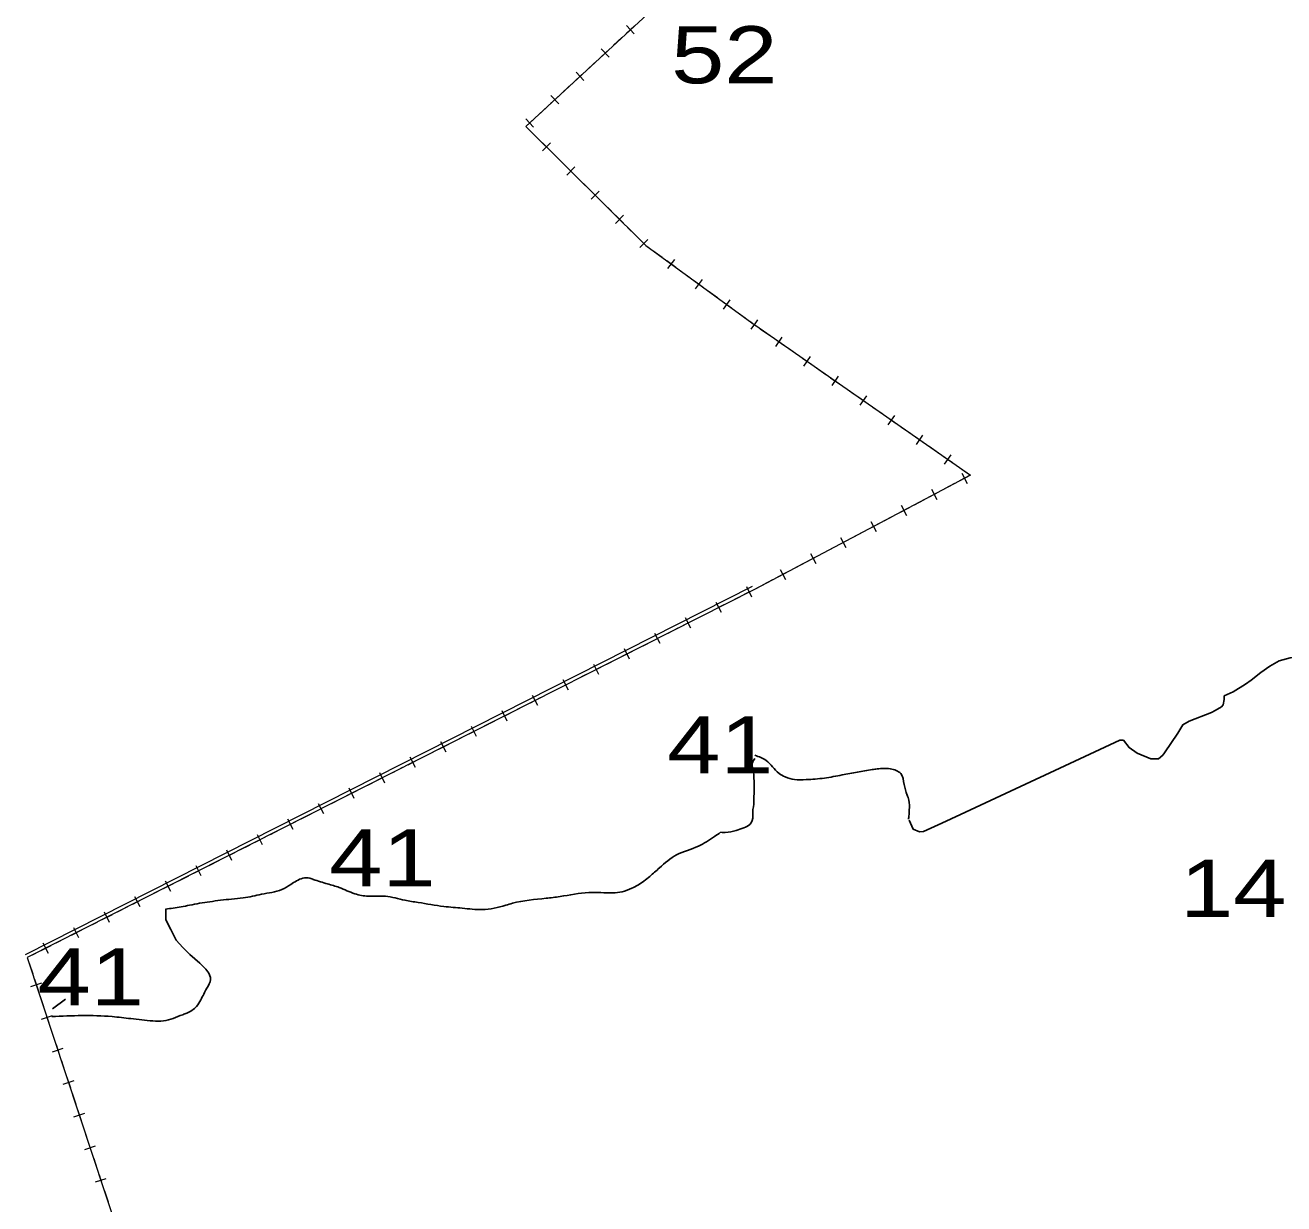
# Model space of a CAD drawing. Extents: x 476989 to 498418, y 4381813 to 4416555.
# Drawn here: x 483464 to 484565, y 4384627 to 4385658 of the extents above; entities that cross this region are included whole.
import ezdxf
from ezdxf.enums import TextEntityAlignment as Align

# ---------------------------------------------------------------- set-up
doc = ezdxf.new("R2010")
doc.units = 0
doc.header["$LTSCALE"] = 20
for name, color, linetype, lineweight in [('13', 7, 'Continuous', 13), ('34', 7, 'Continuous', 13), ('6', 7, 'Continuous', 25)]:
    doc.layers.add(name, color=color, linetype=linetype, lineweight=lineweight)

msp = doc.modelspace()

# ---------------------------------------------------------------- linework, layer by layer
at = {"layer": '34'}
for p, q in [((483986.15, 4385646.82), (483978.81, 4385640.03)), ((483997.17, 4385657), (483989.82, 4385650.21)), ((483990.1, 4385657.28), (483996.89, 4385649.94)), ((483975.14, 4385636.64), (483967.8, 4385629.85)), ((483968.07, 4385636.91), (483974.86, 4385629.57)), ((483964.13, 4385626.45), (483956.79, 4385619.66)), ((483953.11, 4385616.27), (483945.77, 4385609.48)), ((483946.05, 4385616.54), (483952.84, 4385609.2)), ((483942.1, 4385606.08), (483934.76, 4385599.29)), ((483931.09, 4385595.9), (483923.75, 4385589.11)), ((483924.02, 4385596.18), (483930.81, 4385588.83)), ((483920.08, 4385585.71), (483912.73, 4385578.93)), ((483902, 4385575.81), (483908.79, 4385568.47)), ((483905.82, 4385565.21), (483912.93, 4385558.18)), ((483916.48, 4385554.66), (483923.58, 4385547.62)), ((483916.51, 4385547.59), (483923.55, 4385554.69)), ((483927.14, 4385544.1), (483934.24, 4385537.06)), ((483937.79, 4385533.55), (483944.9, 4385526.51)), ((483937.83, 4385526.48), (483944.87, 4385533.58)), ((483948.45, 4385522.99), (483955.56, 4385515.95)), ((483959.11, 4385512.43), (483966.21, 4385505.4)), ((483959.14, 4385505.36), (483966.18, 4385512.47)), ((483969.77, 4385501.88), (483976.87, 4385494.84)), ((483980.42, 4385491.32), (483987.53, 4385484.29)), ((483980.46, 4385484.25), (483987.49, 4385491.36)), ((483991.08, 4385480.77), (483998.19, 4385473.73)), ((484001.77, 4385463.14), (484008.81, 4385470.25)), ((484013.14, 4385460.53), (484021.22, 4385454.63)), ((484025.26, 4385451.69), (484033.34, 4385445.8)), ((484026.35, 4385444.7), (484032.24, 4385452.78)), ((484037.38, 4385442.85), (484045.46, 4385436.96)), ((484049.5, 4385434.01), (484057.58, 4385428.12)), ((484050.59, 4385427.03), (484056.48, 4385435.11)), ((484061.62, 4385425.18), (484069.7, 4385419.28)), ((484073.74, 4385416.34), (484081.82, 4385410.45)), ((484074.83, 4385409.35), (484080.72, 4385417.43)), ((484085.86, 4385407.5), (484093.94, 4385401.61)), ((484097.98, 4385398.66), (484103, 4385395)), ((484099.07, 4385391.68), (484103.23, 4385397.38)), ((484103.23, 4385397.38), (484104.96, 4385399.76)), ((484107.1, 4385392.14), (484115.31, 4385386.42)), ((484119.41, 4385383.57), (484127.61, 4385377.85)), ((484120.65, 4385376.61), (484126.37, 4385384.81)), ((484131.72, 4385374.99), (484139.92, 4385369.27)), ((484144.02, 4385366.41), (484152.23, 4385360.7)), ((484145.27, 4385359.45), (484150.98, 4385367.66)), ((484156.33, 4385357.84), (484164.53, 4385352.12)), ((484169.88, 4385342.3), (484175.6, 4385350.51)), ((484168.64, 4385349.26), (484176.84, 4385343.55)), ((484180.94, 4385340.69), (484189.15, 4385334.97)), ((484193.25, 4385332.11), (484201.46, 4385326.4)), ((484194.49, 4385325.15), (484200.21, 4385333.36)), ((484205.56, 4385323.54), (484213.76, 4385317.82)), ((484217.86, 4385314.96), (484226.07, 4385309.24)), ((484219.11, 4385308), (484224.83, 4385316.21)), ((484230.17, 4385306.39), (484238.38, 4385300.67)), ((484242.48, 4385297.81), (484250.68, 4385292.09)), ((484243.72, 4385290.85), (484249.44, 4385299.05)), ((484254.79, 4385289.23), (484262.99, 4385283.52)), ((484267.09, 4385280.66), (484275.3, 4385274.94)), ((484268.34, 4385273.7), (484274.05, 4385281.9)), ((484279.4, 4385272.08), (484287.6, 4385266.37)), ((484290.24, 4385263.6), (484281.4, 4385258.92)), ((484283.48, 4385265.68), (484288.16, 4385256.84)), ((484256.96, 4385251.65), (484261.64, 4385242.81)), ((484276.98, 4385256.58), (484268.14, 4385251.91)), ((484250.46, 4385242.55), (484241.62, 4385237.88)), ((484263.72, 4385249.57), (484254.88, 4385244.89)), ((484223.95, 4385228.52), (484215.11, 4385223.85)), ((484237.21, 4385235.54), (484228.37, 4385230.86)), ((484230.45, 4385237.62), (484235.12, 4385228.78)), ((484210.69, 4385221.51), (484201.85, 4385216.83)), ((484203.93, 4385223.59), (484208.61, 4385214.75)), ((484184.17, 4385207.48), (484175.33, 4385202.8)), ((484177.41, 4385209.56), (484182.09, 4385200.72)), ((484197.43, 4385214.49), (484188.59, 4385209.82)), ((484150.9, 4385195.53), (484155.57, 4385186.69)), ((484170.91, 4385200.46), (484162.07, 4385195.79)), ((484144.4, 4385186.43), (484135.56, 4385181.75)), ((484157.65, 4385193.45), (484148.82, 4385188.77)), ((484131.14, 4385179.42), (484122.3, 4385174.74)), ((484124.38, 4385181.5), (484129.06, 4385172.66)), ((484100.12, 4385166.55), (483464.12, 4384844.55)), ((484100.12, 4385166.55), (483464.12, 4384844.55)), ((484102, 4385164), (483466, 4384842)), ((484102, 4385164), (484093.09, 4385159.49)), ((484099.81, 4385157.29), (484095.29, 4385166.21)), ((484102.72, 4385164.38), (484102, 4385164)), ((484102.72, 4385164.38), (484102, 4385164)), ((484104.62, 4385165.39), (484102.72, 4385164.38)), ((484117.88, 4385172.4), (484109.04, 4385167.72)), ((484073.05, 4385143.74), (484068.53, 4385152.66)), ((484088.63, 4385157.23), (484079.7, 4385152.71)), ((484061.87, 4385143.68), (484052.95, 4385139.17)), ((484075.25, 4385150.46), (484066.33, 4385145.94)), ((484035.11, 4385130.14), (484026.19, 4385125.62)), ((484048.5, 4385136.91), (484039.57, 4385132.39)), ((484046.29, 4385130.19), (484041.78, 4385139.11)), ((484021.74, 4385123.37), (484012.82, 4385118.85)), ((484019.54, 4385116.65), (484015.02, 4385125.57)), ((483994.98, 4385109.82), (483986.06, 4385105.3)), ((483992.78, 4385103.1), (483988.26, 4385112.02)), ((484008.36, 4385116.59), (483999.44, 4385112.07)), ((483968.23, 4385096.27), (483959.31, 4385091.76)), ((483966.03, 4385089.55), (483961.51, 4385098.47)), ((483981.6, 4385103.04), (483972.68, 4385098.53)), ((483954.85, 4385089.5), (483945.92, 4385084.98)), ((483928.09, 4385075.95), (483919.17, 4385071.43)), ((483941.47, 4385082.73), (483932.55, 4385078.21)), ((483939.27, 4385076.01), (483934.75, 4385084.93)), ((483914.72, 4385069.18), (483905.79, 4385064.66)), ((483912.51, 4385062.46), (483908, 4385071.38)), ((483887.96, 4385055.63), (483879.04, 4385051.12)), ((483885.76, 4385048.91), (483881.24, 4385057.84)), ((483901.33, 4385062.4), (483892.41, 4385057.89)), ((483861.2, 4385042.09), (483852.28, 4385037.57)), ((483859, 4385035.37), (483854.48, 4385044.29)), ((483874.58, 4385048.86), (483865.65, 4385044.34)), ((483832.24, 4385021.82), (483827.73, 4385030.74)), ((483847.82, 4385035.31), (483838.9, 4385030.79)), ((483821.06, 4385021.77), (483812.14, 4385017.25)), ((483834.45, 4385028.54), (483825.52, 4385024.02)), ((483794.31, 4385008.22), (483785.39, 4385003.7)), ((483807.69, 4385014.99), (483798.77, 4385010.48)), ((483805.49, 4385008.27), (483800.97, 4385017.2)), ((483780.93, 4385001.45), (483772.01, 4384996.93)), ((483778.73, 4384994.73), (483774.21, 4385003.65)), ((483754.18, 4384987.9), (483745.26, 4384983.38)), ((483751.98, 4384981.18), (483747.46, 4384990.1)), ((483767.55, 4384994.67), (483758.63, 4384990.16)), ((483725.22, 4384967.64), (483720.7, 4384976.56)), ((483740.8, 4384981.13), (483731.87, 4384976.61)), ((483714.04, 4384967.58), (483705.12, 4384963.06)), ((483727.42, 4384974.36), (483718.5, 4384969.84)), ((483687.28, 4384954.03), (483678.36, 4384949.52)), ((483700.67, 4384960.81), (483691.74, 4384956.29)), ((483698.46, 4384954.09), (483693.95, 4384963.01)), ((483673.91, 4384947.26), (483664.99, 4384942.75)), ((483671.71, 4384940.54), (483667.19, 4384949.46)), ((483647.15, 4384933.72), (483638.23, 4384929.2)), ((483644.95, 4384927), (483640.43, 4384935.92)), ((483660.53, 4384940.49), (483651.61, 4384935.97)), ((483620.4, 4384920.17), (483611.48, 4384915.65)), ((483618.19, 4384913.45), (483613.68, 4384922.37)), ((483633.77, 4384926.94), (483624.85, 4384922.42)), ((483607.01, 4384913.39), (483598.09, 4384908.88)), ((483580.26, 4384899.85), (483571.34, 4384895.33)), ((483593.64, 4384906.62), (483584.72, 4384902.11)), ((483591.44, 4384899.9), (483586.92, 4384908.83)), ((483566.88, 4384893.08), (483557.96, 4384888.56)), ((483564.68, 4384886.36), (483560.17, 4384895.28)), ((483540.13, 4384879.53), (483531.21, 4384875.01)), ((483537.93, 4384872.81), (483533.41, 4384881.73)), ((483553.5, 4384886.3), (483544.58, 4384881.78)), ((483513.37, 4384865.98), (483504.45, 4384861.47)), ((483511.17, 4384859.26), (483506.65, 4384868.19)), ((483526.75, 4384872.75), (483517.82, 4384868.24)), ((483484.41, 4384845.72), (483479.9, 4384854.64)), ((483499.99, 4384859.21), (483491.07, 4384854.69)), ((483473.23, 4384845.66), (483466, 4384842)), ((483486.62, 4384852.44), (483477.69, 4384847.92)), ((483466, 4384842), (483699.09, 4384136.76)), ((483467.57, 4384837.25), (483470.71, 4384827.76)), ((483472.28, 4384823.01), (483475.41, 4384813.52)), ((483469.1, 4384816.69), (483478.59, 4384819.83)), ((483476.98, 4384808.77), (483480.12, 4384799.27)), ((483478.51, 4384788.21), (483488.01, 4384791.35)), ((483481.69, 4384794.53), (483484.83, 4384785.03)), ((483486.4, 4384780.28), (483489.54, 4384770.79)), ((483491.11, 4384766.04), (483494.24, 4384756.55)), ((483487.93, 4384759.72), (483497.42, 4384762.86)), ((483495.81, 4384751.8), (483498.95, 4384742.3)), ((483497.34, 4384731.24), (483506.84, 4384734.38)), ((483500.52, 4384737.56), (483503.66, 4384728.06)), ((483505.23, 4384723.31), (483508.37, 4384713.82)), ((483506.76, 4384702.76), (483516.25, 4384705.89)), ((483509.94, 4384709.07), (483513.07, 4384699.58)), ((483514.64, 4384694.83), (483517.78, 4384685.34)), ((483519.35, 4384680.59), (483522.49, 4384671.09)), ((483516.17, 4384674.27), (483525.67, 4384677.41)), ((483524.06, 4384666.35), (483527.2, 4384656.85)), ((483525.59, 4384645.79), (483535.08, 4384648.93)), ((483528.76, 4384652.1), (483531.9, 4384642.61)), ((483533.47, 4384637.86), (483536.61, 4384628.37))]:
    msp.add_line(p, q, dxfattribs=at)
for points in [[(483872.5, 4386448.65), (483868, 4386266), (483874, 4385990), (483911, 4385821), (484074, 4385832), (484088, 4385741), (483902, 4385569), (484007, 4385465), (484103, 4385395), (484103.22, 4385394.84)], [(483909.06, 4385575.53), (483902, 4385569), (483902.27, 4385568.73)], [(484001.74, 4385470.21), (484007, 4385465), (484009.1, 4385463.47)], [(484103.22, 4385394.84), (484291, 4385264), (484102.72, 4385164.38)]]:
    msp.add_lwpolyline(points, dxfattribs=at)
at = {"layer": '6'}
msp.add_line((483487.94, 4384797.22), (483499.52, 4384805.78), dxfattribs=at)
for points in [[(484560.92, 4385101.66), (484570.5, 4385104.22), (484580.6, 4385105.21), (484596.61, 4385106.51), (484618.44, 4385108.14), (484667.62, 4385110.91), (484693.66, 4385111.99), (484721.33, 4385113.65)], [(484560.92, 4385101.66), (484552.79, 4385097.07), (484544.91, 4385091.31), (484536.45, 4385084.76), (484531.54, 4385081.19), (484520.76, 4385074.46), (484512.97, 4385071.07)], [(484512.97, 4385071.07), (484512.88, 4385067.92), (484512.1, 4385063.1), (484510.53, 4385061.38), (484505.04, 4385058.19), (484501.9, 4385056.36), (484482.31, 4385048.73), (484476.84, 4385045.76), (484472.32, 4385038.32), (484460.76, 4385021.04), (484459.08, 4385019.18)], [(484459.08, 4385019.18), (484455.39, 4385016.01), (484448.82, 4385016.01), (484436.64, 4385020.7), (484429.76, 4385025.69), (484424.76, 4385032.25), (484421.64, 4385032.25), (484282.12, 4384967.05), (484265.88, 4384959.56), (484249.94, 4384952.38), (484246.29, 4384952.07), (484240.98, 4384954.25), (484237.23, 4384962.37)], [(483587.08, 4384884.42), (483587.05, 4384881.67), (483587.05, 4384875.1), (483591.44, 4384866.7), (483596.19, 4384857.2), (483602.04, 4384850.99), (483608.25, 4384844.79), (483617.02, 4384837.12), (483622.14, 4384832), (483624.7, 4384828.35), (483626.16, 4384824.7)]]:
    msp.add_lwpolyline(points, dxfattribs=at)
for points in [[(484072.71, 4384951.59), (484076.5, 4384951.46), (484085.91, 4384953.29), (484092.76, 4384955.65), (484097.86, 4384958.35), (484100.69, 4384966.27), (484100.68, 4384971.57), (484101.12, 4384973.91), (484101.59, 4384983.01), (484101.76, 4384992.72), (484101.64, 4384996.31), (484100.61, 4385007.16), (484100.17, 4385012.34), (484102.4, 4385016.18)], [(484102.41, 4385018.95), (484112.24, 4385014.43), (484123.49, 4385003.19), (484128.93, 4385000.06), (484136.94, 4384997.86), (484147.17, 4384997.68), (484163.2, 4384999.01), (484178.72, 4385001.76), (484191.97, 4385004.19), (484205.12, 4385006.55), (484209.27, 4385007.05), (484220.87, 4385007.19), (484229.91, 4385002.93), (484233.01, 4384993.54), (484235.57, 4384984.24), (484237.09, 4384979.61), (484237.41, 4384971.23), (484237.15, 4384965.97), (484236.81, 4384962.99)], [(483716.09, 4384910.37), (483728.56, 4384906.5), (483738.81, 4384903.36), (483752.37, 4384897.87), (483764.13, 4384895.72), (483779.16, 4384895.71), (483796.36, 4384892.11), (483807.84, 4384890.22), (483830.33, 4384886.7), (483846.47, 4384885.23), (483863.98, 4384883.97), (483884.43, 4384887.78), (483890.35, 4384889.54), (483919.76, 4384893.88), (483931.93, 4384895.43), (483957.16, 4384898.9), (483978.14, 4384898.71), (483986.19, 4384899.52), (483994.88, 4384902.79), (484000, 4384905.38), (484010.44, 4384913.01), (484018.97, 4384920.5), (484033.93, 4384931.86), (484052.96, 4384939.49), (484067.04, 4384947.89), (484072.38, 4384951.59)], [(483716.44, 4384910.09), (483713.2, 4384911.45), (483706.93, 4384911.47), (483696.46, 4384905.89), (483688.57, 4384901.53), (483670.94, 4384897.44), (483654.77, 4384894.2), (483644.64, 4384893.16), (483625.55, 4384890.89), (483607.97, 4384887.86), (483600.49, 4384886.38), (483586.8, 4384884.38)], [(483487.33, 4384790.49), (483540.08, 4384790.42), (483556.51, 4384788.6), (483575.76, 4384786.62), (483585.08, 4384786.62), (483601.9, 4384792.09), (483605.46, 4384793.49), (483613.98, 4384799.33), (483617.78, 4384805.09), (483622.97, 4384815.2), (483626.22, 4384822.95), (483626.1, 4384824.59)]]:
    msp.add_spline(points, degree=3, dxfattribs=at)

# ---------------------------------------------------------------- texts
at = {"layer": '13', "width": 1.25}
for s, p in [('52', (484075.65, 4385606.73)), ('41', (484072.15, 4385003.14)), ('41', (483776.57, 4384904.3)), ('14', (484520.76, 4384877.59)), ('41', (483521.45, 4384800.16))]:
    msp.add_text(s, height=50, dxfattribs=at).set_placement(p, align=Align.CENTER)

doc.saveas('drawing.dxf')
